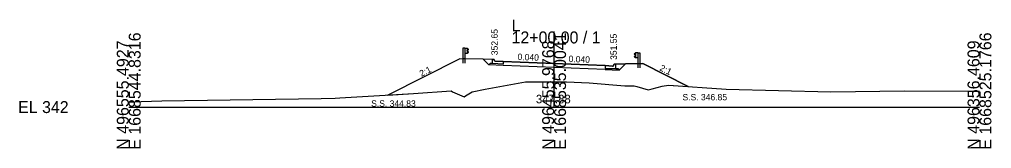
# Model space of a CAD drawing. Extents: x -26 to 203, y -10 to 5517.
# Drawn here: x -25.7 to 202.8, y 1990.3 to 2020.5 of the extents above; entities that cross this region are included whole.
import ezdxf

# ---------------------------------------------------------------- set-up
doc = ezdxf.new("R2010")
doc.units = 0
for name, color, linetype in [('Exist Cross Section Cell', 7, 'Continuous'), ('Exist XS Center Line Elevation Label', 7, 'Continuous'), ('Exist XS Ground Line', 7, 'Continuous'), ('Prop XS Earthwork Shape', 7, 'Continuous'), ('Prop XS Finish Grade', 7, 'Continuous'), ('Prop XS Finish Grade CurbGutter', 7, 'Continuous'), ('Prop XS Finish Grade Earthwork', 7, 'Continuous'), ('Prop XS Finish Grade Pavement', 7, 'Continuous'), ('Prop XS Geopak Shape', 7, 'Continuous'), ('Prop XS Hydro Elevations', 7, 'Continuous'), ('Prop XS Pvmt Edge Slope', 7, 'Continuous'), ('Prop XS SE Text', 7, 'Continuous'), ('Prop XS Side Slope Text', 7, 'Continuous'), ('Prop XS SS Elevation Text', 7, 'Continuous'), ('Prop XS Subgrade CurbGutter', 7, 'Continuous'), ('Prop XS Subgrade Earthwork', 7, 'Continuous'), ('Typical Guardrail CELL', 7, 'Continuous')]:
    doc.layers.add(name, color=color, linetype=linetype)

msp = doc.modelspace()

# ---------------------------------------------------------------- linework, layer by layer
at = {"layer": 'Exist Cross Section Cell'}
for p, q in [((100, 2000), (100, 2017.71)), ((0, 2000), (100, 2000)), ((100, 2000), (200, 2000))]:
    msp.add_line(p, q, dxfattribs=at)
at = {"layer": 'Exist XS Ground Line'}
for p, q in [((83.8, 2004.19), (93.3, 2005.89)), ((93.3, 2005.89), (95.51, 2005.9)), ((95.51, 2005.9), (100, 2005.88)), ((100, 2005.88), (100.64, 2005.88)), ((100.64, 2005.88), (102.94, 2005.88)), ((102.94, 2005.88), (108.28, 2005.68)), ((108.28, 2005.68), (116.65, 2004.98)), ((116.65, 2004.98), (118.85, 2005.01)), ((118.85, 2005.01), (119.43, 2004.83)), ((119.43, 2004.83), (122.11, 2004.02)), ((122.11, 2004.02), (123.06, 2004.27)), ((123.06, 2004.27), (125.43, 2004.91)), ((125.43, 2004.91), (126.93, 2005.16)), ((126.93, 2005.16), (140.42, 2004.23)), ((7.78, 2001.5), (45.24, 2001.98)), ((45.24, 2001.98), (48.52, 2002.07)), ((48.52, 2002.07), (49.6, 2002.14)), ((49.6, 2002.14), (66.95, 2003.19)), ((66.95, 2003.19), (75.78, 2003.79)), ((75.78, 2003.79), (76.12, 2003.61)), ((76.12, 2003.61), (78.89, 2002.43)), ((78.89, 2002.43), (79.19, 2002.64)), ((79.19, 2002.64), (80.73, 2003.61)), ((80.73, 2003.61), (83.8, 2004.19)), ((140.42, 2004.23), (165.08, 2003.56)), ((165.08, 2003.56), (182.4, 2003.83)), ((182.4, 2003.83), (197.32, 2003.74)), ((197.32, 2003.74), (200, 2003.73)), ((0, 2001.15), (2.89, 2001.28)), ((2.89, 2001.28), (7.78, 2001.5))]:
    msp.add_line(p, q, dxfattribs=at)
at = {"layer": 'Prop XS Earthwork Shape'}
msp.add_lwpolyline([(60.88, 2002.83), (66.95, 2003.19), (75.78, 2003.79), (76.12, 2003.61), (78.89, 2002.43), (79.19, 2002.64), (80.73, 2003.61), (83.8, 2004.19), (93.3, 2005.89), (95.51, 2005.9), (100, 2005.88), (100.64, 2005.88), (102.94, 2005.88), (108.28, 2005.68), (116.65, 2004.98), (118.85, 2005.01), (119.43, 2004.83), (122.11, 2004.02), (123.06, 2004.27), (125.43, 2004.91), (126.93, 2005.16), (131.51, 2004.85), (120.83, 2010.18), (116.77, 2010.1), (115.33, 2008.66), (112, 2008.79), (100, 2009.27), (88, 2009.76), (84.67, 2009.89), (83.36, 2011.2), (77.86, 2011.31)], close=True, dxfattribs=at)
at = {"layer": 'Prop XS Finish Grade'}
for p, q in [((85.5, 2011.15), (83.36, 2011.2)), ((114.5, 2010.05), (116.77, 2010.1))]:
    msp.add_line(p, q, dxfattribs=at)
at = {"layer": 'Prop XS Finish Grade CurbGutter'}
for p, q in [((85.5, 2011.15), (85.75, 2011.15)), ((85.75, 2011.15), (85.88, 2011.11)), ((85.97, 2011.02), (85.88, 2011.11)), ((86.03, 2010.77), (85.97, 2011.02)), ((86.13, 2010.68), (86.03, 2010.77)), ((86.25, 2010.65), (86.13, 2010.68)), ((88, 2010.67), (86.25, 2010.65)), ((112, 2009.71), (113.75, 2009.57)), ((113.75, 2009.57), (113.87, 2009.59)), ((113.87, 2009.59), (113.97, 2009.69)), ((113.97, 2009.69), (114.03, 2009.94)), ((114.03, 2009.94), (114.12, 2010.03)), ((114.25, 2010.05), (114.12, 2010.03)), ((114.5, 2010.05), (114.25, 2010.05))]:
    msp.add_line(p, q, dxfattribs=at)
at = {"layer": 'Prop XS Finish Grade Earthwork'}
for p, q in [((77.86, 2011.31), (60.88, 2002.83)), ((83.36, 2011.2), (77.86, 2011.31)), ((116.77, 2010.1), (120.83, 2010.18)), ((120.83, 2010.18), (131.51, 2004.85))]:
    msp.add_line(p, q, dxfattribs=at)
at = {"layer": 'Prop XS Finish Grade Pavement'}
for p, q in [((88, 2010.67), (100, 2010.19)), ((100, 2010.19), (112, 2009.71))]:
    msp.add_line(p, q, dxfattribs=at)
at = {"layer": 'Prop XS Geopak Shape'}
msp.add_lwpolyline([(85.5, 2011.15), (83.36, 2011.2), (77.86, 2011.31), (60.88, 2002.83), (66.95, 2003.19), (75.78, 2003.79), (76.12, 2003.61), (78.89, 2002.43), (79.19, 2002.64), (80.73, 2003.61), (83.8, 2004.19), (93.3, 2005.89), (95.51, 2005.9), (100, 2005.88), (100.64, 2005.88), (102.94, 2005.88), (108.28, 2005.68), (116.65, 2004.98), (118.85, 2005.01), (119.43, 2004.83), (122.11, 2004.02), (123.06, 2004.27), (125.43, 2004.91), (126.93, 2005.16), (131.51, 2004.85), (120.83, 2010.18), (116.77, 2010.1), (114.5, 2010.05), (114.25, 2010.05), (114.12, 2010.03), (114.03, 2009.94), (113.97, 2009.69), (113.87, 2009.59), (113.75, 2009.57), (112, 2009.71), (100, 2010.19), (88, 2010.67), (86.25, 2010.65), (86.13, 2010.68), (86.03, 2010.77), (85.97, 2011.02), (85.88, 2011.11), (85.75, 2011.15)], close=True, dxfattribs=at)
at = {"layer": 'Prop XS Pvmt Edge Slope'}
for p, q in [((85, 2010.21), (84.67, 2009.89)), ((85.5, 2010.19), (85, 2010.21)), ((114.5, 2009.03), (115, 2009.01)), ((115, 2009.01), (115.33, 2008.66))]:
    msp.add_line(p, q, dxfattribs=at)
at = {"layer": 'Prop XS Subgrade CurbGutter'}
for p, q in [((85.5, 2010.19), (85.5, 2011.15)), ((88, 2010.09), (85.5, 2010.19)), ((88, 2010.67), (88, 2010.09)), ((112, 2009.71), (112, 2009.13)), ((112, 2009.13), (114.5, 2009.03)), ((114.5, 2009.03), (114.5, 2010.05))]:
    msp.add_line(p, q, dxfattribs=at)
at = {"layer": 'Prop XS Subgrade Earthwork'}
for p, q in [((84.67, 2009.89), (83.36, 2011.2)), ((88, 2009.76), (84.67, 2009.89)), ((88, 2009.75), (88, 2009.76)), ((100, 2009.27), (88, 2009.75)), ((112, 2008.79), (100, 2009.27)), ((115.33, 2008.66), (116.77, 2010.1)), ((112, 2008.79), (112, 2008.8)), ((112, 2008.8), (115.33, 2008.66))]:
    msp.add_line(p, q, dxfattribs=at)
at = {"layer": 'Typical Guardrail CELL'}
for p, q in [((79.04, 2013.77), (78.54, 2013.77)), ((78.54, 2013.77), (78.54, 2011.29)), ((79.04, 2013.77), (79.04, 2011.29)), ((79.04, 2013.77), (79.54, 2013.77)), ((79.54, 2013.77), (79.54, 2012.61)), ((79.54, 2013.77), (79.82, 2013.57)), ((79.54, 2013.24), (79.82, 2013.44)), ((79.04, 2011.29), (78.54, 2011.29)), ((78.54, 2011.29), (78.54, 2010.28)), ((79.04, 2012.61), (79.54, 2012.61)), ((79.04, 2011.29), (79.04, 2010.28)), ((79.54, 2013.19), (79.54, 2013.24)), ((79.54, 2013.19), (79.54, 2013.15)), ((79.54, 2013.15), (79.82, 2012.94)), ((79.54, 2012.61), (79.82, 2012.82)), ((119.16, 2012.7), (118.87, 2012.5)), ((119.16, 2012.17), (118.87, 2012.37)), ((119.16, 2012.08), (118.87, 2011.88)), ((119.16, 2011.54), (118.87, 2011.75)), ((119.65, 2012.7), (119.16, 2012.7)), ((119.16, 2012.7), (119.16, 2011.54)), ((119.16, 2012.12), (119.16, 2012.17)), ((119.16, 2012.12), (119.16, 2012.08)), ((119.65, 2011.54), (119.16, 2011.54)), ((119.65, 2012.7), (119.65, 2010.22)), ((119.65, 2012.7), (120.15, 2012.7)), ((120.15, 2012.7), (120.15, 2010.22)), ((119.65, 2010.22), (120.15, 2010.22)), ((119.65, 2010.22), (119.65, 2009.21)), ((120.15, 2010.22), (120.15, 2009.21))]:
    msp.add_line(p, q, dxfattribs=at)
for centre, start, end in [((79.78, 2013.51), 304.9888, 54.997), ((79.78, 2012.88), 304.9634, 54.9941), ((118.91, 2012.44), 125.003, 235.0112), ((118.91, 2011.81), 125.0059, 235.0366)]:
    msp.add_arc(centre, 0.0776, start, end, dxfattribs=at)

# ---------------------------------------------------------------- texts
at = {"layer": 'Exist Cross Section Cell'}
for s, p in [('L', (90, 2017.71)), ('12+00.00 / 1', (90, 2014.91)), ('EL 342', (-26, 1998.6))]:
    msp.add_text(s, height=2.8, dxfattribs=at).set_placement(p)
for s, p in [('E 1668544.8316', (2.8, 1990)), ('E 1668535.0041', (102.8, 1990)), ('E 1668525.1766', (202.8, 1990)), ('N 496555.4927', (0, 1990)), ('N 496455.9768', (100, 1990)), ('N 496356.4609', (200, 1990))]:
    msp.add_text(s, height=2.8, rotation=90, dxfattribs=at).set_placement(p)
at = {"layer": 'Exist XS Center Line Elevation Label'}
msp.add_text('347.88', height=2, dxfattribs=at).set_placement((95.73, 2000.88))
at = {"layer": 'Prop XS Hydro Elevations'}
for s, p in [('352.65', (86.75, 2012.15)), ('351.55', (114.75, 2011.05))]:
    msp.add_text(s, height=1.5, rotation=90, dxfattribs=at).set_placement(p)
at = {"layer": 'Prop XS SE Text'}
for p in [(91.38, 2011.04), (103.38, 2010.56)]:
    msp.add_text('0.040', height=1.5, rotation=357.7094, dxfattribs=at).set_placement(p)
at = {"layer": 'Prop XS Side Slope Text'}
for rotation, p in [(26.5651, (68.8, 2007.06)), (333.4349, (124.67, 2008.68))]:
    msp.add_text('2:1', height=1.5, rotation=rotation, dxfattribs=at).set_placement(p)
at = {"layer": 'Prop XS SS Elevation Text'}
for s, p in [('S.S. 346.85', (130.18, 2001.58)), ('S.S. 344.83', (56.99, 2000.09))]:
    msp.add_text(s, height=1.5, dxfattribs=at).set_placement(p)

doc.saveas('drawing.dxf')
